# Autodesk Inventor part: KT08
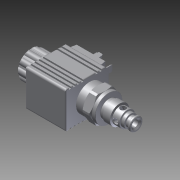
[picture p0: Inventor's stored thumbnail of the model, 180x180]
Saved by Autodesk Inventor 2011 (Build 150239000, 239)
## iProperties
Created: 2012-01
Part Number: KT08
Document SubType Name: Modeling
Designer: khramov
Density: 1 g/cm^3
Author: khramov
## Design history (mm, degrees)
derived "KT08_2NC_10N_D24K1.iam"
node "Твердое тело1"
node "190274.ipt:1"
node "02696101.ipt:1"
node "0134091.ipt:1"
node "0532067_DIN_1481_3_5x10.ipt:1"
node "0134090.ipt:1"
node "0119382.ipt:1"
